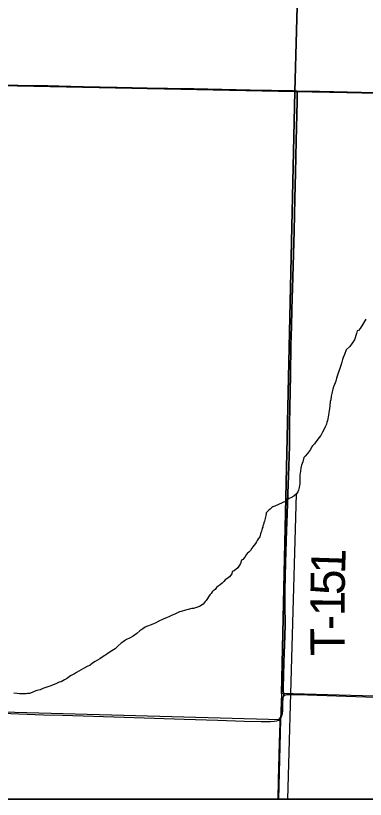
# Model space of a CAD drawing. Extents: x 2.4 to 73.1, y 4.5 to 25.6.
# Drawn here: x 33.235 to 33.525, y 17.985 to 18.636 of the extents above; entities that cross this region are included whole.
import ezdxf

# ---------------------------------------------------------------- set-up
doc = ezdxf.new("R2010")
doc.units = 0
for name, color, linetype in [('GM_X_Interchange_Ramps', 7, 'Continuous'), ('GM_X_Minor_River', 7, 'Continuous'), ('GM_X_Section', 7, 'Continuous'), ('GM_X_Township_Road', 7, 'Continuous'), ('GM_X_Township_Road_Text', 7, 'Continuous'), ('GM_X_US_Shield', 7, 'Continuous'), ('SH_Cut_Line', 7, 'Continuous'), ('SH_Data', 7, 'Continuous')]:
    doc.layers.add(name, color=color, linetype=linetype)

msp = doc.modelspace()

# ---------------------------------------------------------------- linework, layer by layer
at = {"layer": 'GM_X_Interchange_Ramps'}
for points in [[(30.40528, 17.98522), (33.45306, 17.98522), (33.45346, 18.00132), (33.45429, 18.03239), (33.45481, 18.04891), (33.45475, 18.04944), (33.45467, 18.04998), (33.45409, 18.05166), (33.45485, 18.05272), (33.45496, 18.0529), (33.4555, 18.05377), (33.45614, 18.05522), (33.45649, 18.05676), (33.45666, 18.05833), (33.45677, 18.06152), (33.4568, 18.06632), (33.45689, 18.0679), (33.45712, 18.06946), (33.45729, 18.07027), (33.45754, 18.07091), (33.45804, 18.07169), (33.45752, 18.07369), (33.45735, 18.07494), (33.45722, 18.07637), (33.45723, 18.07765), (33.45762, 18.08853), (33.45793, 18.09941), (33.45879, 18.12118), (33.45901, 18.13051), (33.45879, 18.14607), (33.45864, 18.15851), (33.45922, 18.18184), (33.46013, 18.20827), (33.46047, 18.22227), (33.46109, 18.23937), (33.46164, 18.25336), (33.46241, 18.27824), (33.46245, 18.28758), (33.46256, 18.29691), (33.46335, 18.33735), (33.46375, 18.36224), (33.46414, 18.3778), (33.46449, 18.39179), (33.46534, 18.41823), (33.46632, 18.45711), (33.4669, 18.48356), (33.46748, 18.50533), (33.46818, 18.53177), (33.46884, 18.56444), (33.46886, 18.57066), (33.46887, 18.57311), (33.46557, 18.5732), (33.42984, 18.57389), (33.38323, 18.57485), (33.36149, 18.57528), (33.3444, 18.57552), (33.31954, 18.57597), (33.29158, 18.57667), (33.27139, 18.57711), (33.26207, 18.5773), (33.2543, 18.57732), (33.23721, 18.57757), (33.22171, 18.578)], [(33.53392, 18.57174), (33.48732, 18.57272), (33.46887, 18.57311), (33.46886, 18.57066), (33.46884, 18.56444), (33.46818, 18.53177), (33.46748, 18.50533), (33.4669, 18.48356), (33.46632, 18.45711), (33.46534, 18.41823), (33.46449, 18.39179), (33.46414, 18.3778), (33.46375, 18.36224), (33.46335, 18.33735), (33.46256, 18.29691), (33.46245, 18.28758), (33.46241, 18.27824), (33.46164, 18.25336), (33.46109, 18.23937), (33.46047, 18.22227), (33.46013, 18.20827), (33.45922, 18.18184), (33.45864, 18.15851), (33.45879, 18.14607), (33.45901, 18.13051), (33.45879, 18.12118), (33.45793, 18.09941), (33.45762, 18.08853), (33.45723, 18.07765), (33.45722, 18.07637), (33.45735, 18.07494), (33.45752, 18.07369), (33.45804, 18.07169), (33.45754, 18.07091), (33.45729, 18.07027), (33.45712, 18.06946), (33.45689, 18.0679), (33.4568, 18.06632), (33.45677, 18.06152), (33.45666, 18.05833), (33.45649, 18.05676), (33.45614, 18.05522), (33.4555, 18.05377), (33.45496, 18.0529), (33.45485, 18.05272), (33.45409, 18.05166), (33.45467, 18.04998), (33.45475, 18.04944), (33.45481, 18.04891), (33.45429, 18.03239), (33.45346, 18.00132), (33.45306, 17.98522), (36.29738, 17.98522)]]:
    msp.add_lwpolyline(points, dxfattribs=at)
at = {"layer": 'GM_X_Minor_River'}
msp.add_line((33.46128, 17.98522), (33.46835, 18.23865), dxfattribs=at)
for points in [[(33.52583, 18.38388), (33.52335, 18.37951), (33.52106, 18.3761), (33.51973, 18.37439), (33.51859, 18.37402), (33.5184, 18.37288), (33.51801, 18.37174), (33.51648, 18.36661), (33.51267, 18.36111), (33.50943, 18.35827), (33.5081, 18.35447), (33.50714, 18.35181), (33.50638, 18.3503), (33.5058, 18.34802), (33.50504, 18.34517), (33.50236, 18.33738), (33.5016, 18.33491), (33.50083, 18.33226), (33.49988, 18.3296), (33.49911, 18.32751), (33.49854, 18.32561), (33.49796, 18.32333), (33.49758, 18.322), (33.4972, 18.31991), (33.49681, 18.31687), (33.49624, 18.31535), (33.49585, 18.31174)], [(33.49585, 18.31174), (33.49566, 18.30927), (33.49547, 18.30794), (33.49527, 18.30623), (33.49489, 18.30395), (33.49451, 18.30263), (33.49431, 18.30111), (33.49393, 18.29959), (33.49355, 18.29826), (33.49316, 18.29655), (33.49221, 18.29427), (33.49107, 18.29199), (33.48992, 18.2899), (33.4884, 18.28725), (33.48687, 18.28516), (33.48554, 18.28345), (33.48439, 18.28194), (33.48325, 18.28023), (33.48173, 18.27852), (33.48077, 18.27758), (33.47982, 18.27549), (33.47753, 18.27227), (33.47563, 18.27018), (33.47429, 18.26885), (33.47353, 18.26524), (33.47257, 18.26259), (33.47219, 18.26145), (33.472, 18.26012), (33.4718, 18.25784), (33.47142, 18.25575), (33.47104, 18.25461), (33.47103, 18.25157), (33.47122, 18.24948), (33.47121, 18.24815), (33.47102, 18.24682), (33.47083, 18.24568), (33.47064, 18.24397), (33.47006, 18.24188), (33.46949, 18.24055), (33.46835, 18.23865), (33.46625, 18.23676), (33.46378, 18.23543), (33.46226, 18.23487), (33.4594, 18.23279), (33.45027, 18.22844), (33.44875, 18.22788), (33.44779, 18.22731), (33.44684, 18.22636), (33.44551, 18.22522), (33.44456, 18.22428), (33.44322, 18.22314), (33.44322, 18.22219), (33.44245, 18.21839), (33.44169, 18.21611), (33.44131, 18.21478), (33.44092, 18.21326), (33.44054, 18.21231), (33.44035, 18.21117), (33.43997, 18.21023), (33.43958, 18.2089), (33.4392, 18.20776), (33.43844, 18.20548), (33.43786, 18.2032), (33.43653, 18.2013), (33.43577, 18.19997), (33.43519, 18.19884), (33.43443, 18.19751), (33.43329, 18.19618), (33.43215, 18.19485), (33.43138, 18.19372), (33.43024, 18.19182), (33.42872, 18.1903), (33.42738, 18.18936), (33.42662, 18.18822), (33.42548, 18.18613), (33.42376, 18.18424), (33.42281, 18.18367), (33.42185, 18.18101), (33.41957, 18.1774), (33.41671, 18.17475), (33.415, 18.17419), (33.41461, 18.17248), (33.41271, 18.17001), (33.41061, 18.16812), (33.40928, 18.16736), (33.40814, 18.16603), (33.40662, 18.16471), (33.40509, 18.16338), (33.40338, 18.16206), (33.40205, 18.16092), (33.4009, 18.1594), (33.39938, 18.15827), (33.39843, 18.15732), (33.39766, 18.15618), (33.39652, 18.15485), (33.39538, 18.15334), (33.39462, 18.15182), (33.39347, 18.15011), (33.39252, 18.14935), (33.391, 18.14727), (33.38795, 18.14538)], [(33.38795, 18.14538), (33.38472, 18.14424), (33.38281, 18.14368), (33.38148, 18.14368), (33.37863, 18.14274), (33.37635, 18.14218), (33.37273, 18.14124), (33.3714, 18.14086), (33.3674, 18.13897), (33.36531, 18.13803), (33.36303, 18.1369), (33.36055, 18.13576), (33.35827, 18.13501), (33.35675, 18.13425), (33.35542, 18.13369), (33.3537, 18.13274), (33.35161, 18.1318), (33.34933, 18.13066), (33.34704, 18.12972), (33.34552, 18.12915), (33.344, 18.12878), (33.34286, 18.12802), (33.34095, 18.1267), (33.33848, 18.12499), (33.33581, 18.12291), (33.33296, 18.12064), (33.32991, 18.11894), (33.32744, 18.1178), (33.32573, 18.11686), (33.32458, 18.11591), (33.32306, 18.11477), (33.3204, 18.1125), (33.31792, 18.11023), (33.31526, 18.10852), (33.31297, 18.10701), (33.31107, 18.10569), (33.30935, 18.10455), (33.30726, 18.10323), (33.30517, 18.1019), (33.30326, 18.10077), (33.30136, 18.09963), (33.29927, 18.09831), (33.29717, 18.0966), (33.29413, 18.09528), (33.29184, 18.09377), (33.28975, 18.09263), (33.28785, 18.09169), (33.28594, 18.09055), (33.28423, 18.08942), (33.28252, 18.08866), (33.28157, 18.08809), (33.28023, 18.08715), (33.27833, 18.08582), (33.27605, 18.0845), (33.27319, 18.0828), (33.27167, 18.08242), (33.27034, 18.08185), (33.2692, 18.08129), (33.26463, 18.0794), (33.26311, 18.07884), (33.26121, 18.07827), (33.25968, 18.07789), (33.25797, 18.07733), (33.25569, 18.0762), (33.25302, 18.07544), (33.25093, 18.07469), (33.24903, 18.07393), (33.24694, 18.07318), (33.24541, 18.07299), (33.24427, 18.07281), (33.24313, 18.07281), (33.24199, 18.07281), (33.24047, 18.07282), (33.23876, 18.07282), (33.23667, 18.07302), (33.23401, 18.07322)]]:
    msp.add_lwpolyline(points, dxfattribs=at)
at = {"layer": 'GM_X_Section'}
for points in [[(32.97722, 19.08485), (33.48089, 19.0765), (33.46684, 18.57275), (32.96625, 18.58294)], [(33.9688, 19.06715), (33.95589, 18.56338), (33.46684, 18.57275), (33.48089, 19.0765)], [(32.95129, 18.58326), (32.96625, 18.58294), (33.46684, 18.57275), (33.45592, 18.07311), (33.45507, 18.05115), (32.93411, 18.06556)], [(33.95589, 18.56338), (33.95452, 18.05862), (33.45592, 18.07311), (33.46684, 18.57275)]]:
    msp.add_lwpolyline(points, close=True, dxfattribs=at)
at = {"layer": 'GM_X_Township_Road'}
for points in [[(33.21687, 18.57784), (33.22183, 18.57773), (33.23733, 18.5773), (33.25442, 18.57705), (33.26218, 18.57702), (33.27151, 18.57683), (33.2917, 18.5764), (33.31966, 18.57569), (33.34451, 18.57525), (33.3616, 18.575), (33.38335, 18.57457), (33.42996, 18.57361), (33.46569, 18.57292), (33.46899, 18.57284)], [(33.45816, 18.07141), (33.45764, 18.07341), (33.45747, 18.07467), (33.45734, 18.0761), (33.45734, 18.07737), (33.45774, 18.08825), (33.45805, 18.09914), (33.45891, 18.1209), (33.45913, 18.13023), (33.45891, 18.14579), (33.45876, 18.15824), (33.45933, 18.18157), (33.46024, 18.208), (33.46059, 18.222), (33.46121, 18.2391), (33.46175, 18.25309), (33.46252, 18.27797), (33.46257, 18.2873), (33.46267, 18.29663), (33.46347, 18.33708), (33.46387, 18.36197), (33.46426, 18.37752), (33.46461, 18.39152), (33.46546, 18.41795), (33.46644, 18.45684), (33.46702, 18.48328), (33.4676, 18.50506), (33.4683, 18.5315), (33.46895, 18.56417), (33.46898, 18.57038), (33.46899, 18.57284)], [(33.46899, 18.57284), (33.48743, 18.57245), (33.53404, 18.57146), (33.54491, 18.57148), (33.54634, 18.57149)], [(33.4542, 18.05138), (33.45497, 18.05245), (33.45562, 18.0535), (33.45625, 18.05495), (33.45661, 18.05648), (33.45678, 18.05806), (33.45688, 18.06124), (33.45691, 18.06604), (33.45701, 18.06763), (33.45724, 18.06918), (33.45741, 18.07), (33.45766, 18.07063), (33.45816, 18.07141)], [(33.45816, 18.07141), (33.45871, 18.07172), (33.45948, 18.07197), (33.46041, 18.07213), (33.46194, 18.0723), (33.46504, 18.07236), (33.47747, 18.07198), (33.52563, 18.07025), (33.53806, 18.0698), (33.56292, 18.06925), (33.5971, 18.06821), (33.64215, 18.06661), (33.67011, 18.06564), (33.67309, 18.06554)], [(33.22449, 18.05665), (33.25867, 18.05547), (33.27421, 18.05499), (33.32551, 18.05354), (33.37523, 18.05169), (33.40321, 18.05087), (33.42497, 18.05022), (33.43896, 18.04988), (33.44673, 18.04995), (33.44984, 18.05012), (33.45217, 18.05047), (33.45329, 18.05081), (33.4542, 18.05138)], [(33.45318, 17.98522), (33.45357, 18.00105), (33.45441, 18.03211), (33.45493, 18.04863), (33.45487, 18.04917), (33.45479, 18.0497), (33.4542, 18.05138)]]:
    msp.add_lwpolyline(points, dxfattribs=at)
at = {"layer": 'GM_X_US_Shield'}
for points in [[(33.45332, 17.98522), (33.95239, 17.98522), (33.95452, 18.05862), (33.45592, 18.07311), (33.45507, 18.05115)], [(32.93233, 17.98522), (33.45332, 17.98522), (33.45507, 18.05115), (32.93411, 18.06556)]]:
    msp.add_lwpolyline(points, close=True, dxfattribs=at)
at = {"layer": 'SH_Cut_Line'}
msp.add_lwpolyline([(29.49738, 21.67933), (29.49738, 17.98522), (36.29738, 17.98522), (36.29738, 20.02567)], dxfattribs=at)
at = {"layer": 'SH_Data'}
msp.add_lwpolyline([(29.49738, 24.78522), (36.29738, 24.78522), (36.29738, 17.98522), (29.49738, 17.98522)], close=True, dxfattribs=at)

# ---------------------------------------------------------------- texts
at = {"layer": 'GM_X_Township_Road_Text'}
for s, rotation, p in [('1', 88.08199, (33.50857, 18.17203)), ('5', 89.03717, (33.50828, 18.15466)), ('1', 89.76582, (33.50821, 18.13726)), ('-', 90.23809, (33.50826, 18.12565)), ('T', 90.40072, (33.5084, 18.10442))]:
    msp.add_text(s, height=0.02841, rotation=rotation, dxfattribs=at).set_placement(p)

doc.saveas('drawing.dxf')
